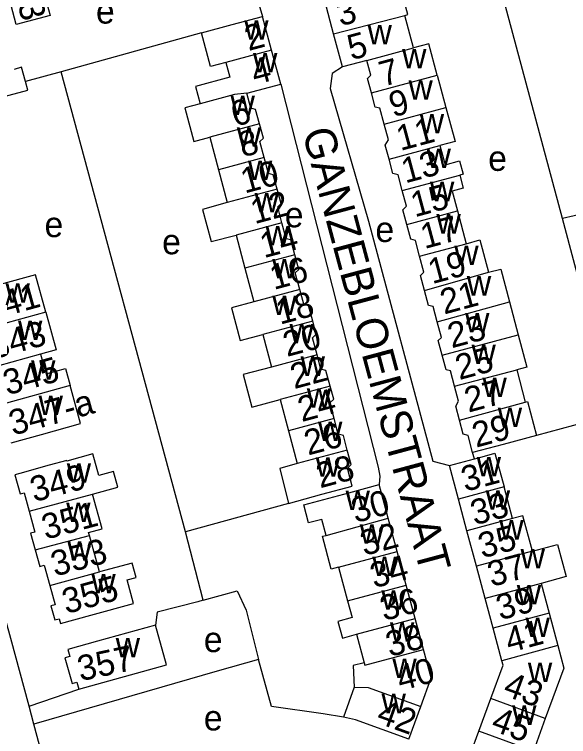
# Model space of a CAD drawing. Extents: x 161258 to 163262, y 380749 to 382054.
# Drawn here: x 162637.4 to 162725.4, y 380891.5 to 381006.1 of the extents above; entities that cross this region are included whole.
import ezdxf

# ---------------------------------------------------------------- set-up
doc = ezdxf.new("R2010")
doc.units = 0
for name, color, linetype in [('BLT_Basislijn', 7, 'Continuous'), ('BLT_Bebouwing', 7, 'Continuous'), ('BLT_Centroide', 7, 'Continuous'), ('BLT_Huisnummer', 7, 'Continuous'), ('BLT_Huisnummer_ tussenligend', 7, 'Continuous'), ('BLT_Huisnummer_reeks', 7, 'Continuous'), ('BLT_Onderverdeling_panden', 7, 'Continuous'), ('BLT_Straatnaam', 7, 'Continuous')]:
    doc.layers.add(name, color=color, linetype=linetype)

msp = doc.modelspace()

# ---------------------------------------------------------------- linework, layer by layer
at = {"layer": 'BLT_Basislijn'}
for p, q in [((162724.48, 380973.67), (162713.31, 381015.17)), ((162674.73, 381012.76), (162676.84, 381005.77)), ((162667.15, 381003.17), (162644.85, 380996.98)), ((162644.85, 380996.98), (162639.18, 380995.41)), ((162664.6, 380923.97), (162644.85, 380996.98)), ((162738.59, 380976.98), (162724.48, 380973.67)), ((162732.68, 380942.59), (162724.48, 380973.67)), ((162732.68, 380942.59), (162720.33, 380939.28)), ((162710.47, 380935.55), (162710.2, 380936.55)), ((162680.95, 380928.49), (162664.6, 380923.97)), ((162667.42, 380913.11), (162664.6, 380923.97)), ((162639.76, 380896.31), (162647.65, 380898.99)), ((162640.53, 380893.46), (162639.76, 380896.31)), ((162646.34, 380871.78), (162640.53, 380893.46))]:
    msp.add_line(p, q, dxfattribs=at)
for points in [[(162689.52, 380997.74), (162687.88, 380996.7), (162687.56, 380994.31), (162693.67, 380973.26), (162703.88, 380935.18), (162706.51, 380934.49)], [(162679.72, 380995.02), (162695.2, 380934.23), (162695.46, 380932.82), (162695.37, 380931.47)], [(162639.76, 380896.31), (162636.88, 380907.05), (162625.03, 380949.86)], [(162667.42, 380913.11), (162672.8, 380914.62), (162674.21, 380911.55), (162676.21, 380903.73)], [(162667.42, 380913.11), (162666.57, 380912.87), (162660.1, 380911.24), (162659.85, 380909.16)], [(162676.21, 380903.73), (162669.64, 380901.86), (162640.53, 380893.46)], [(162689.67, 380894.55), (162686.48, 380895.11), (162678.27, 380896.25), (162676.21, 380903.73)]]:
    msp.add_lwpolyline(points, dxfattribs=at)
at = {"layer": 'BLT_Bebouwing'}
for p, q in [((162688.11, 381002.99), (162686.7, 381008.23)), ((162678.28, 381000.39), (162676.84, 381005.77)), ((162700.82, 381000.78), (162699.43, 381005.93)), ((162689.52, 380997.74), (162688.11, 381002.99)), ((162693.4, 380998.78), (162689.52, 380997.74)), ((162704.57, 380996.45), (162705.95, 380991.32)), ((162674.32, 380993.57), (162679.72, 380995.02)), ((162668.45, 380986.62), (162669.84, 380981.43)), ((162669.84, 380981.43), (162671.24, 380976.22)), ((162707.79, 380974.9), (162709.19, 380969.69)), ((162672.63, 380971.04), (162674.03, 380965.83)), ((162674.03, 380965.83), (162675.47, 380960.45)), ((162716.04, 380960.49), (162717.45, 380955.25)), ((162676.86, 380955.28), (162678.24, 380950.12)), ((162717.19, 380949.69), (162718.54, 380944.53)), ((162679.63, 380944.95), (162680.95, 380940.01)), ((162680.95, 380940.01), (162682.34, 380934.82)), ((162706.51, 380934.49), (162710.47, 380935.55)), ((162707.95, 380929.16), (162706.51, 380934.49)), ((162696.79, 380926.16), (162695.37, 380931.47)), ((162716.52, 380926.09), (162715.18, 380931.1)), ((162709.3, 380924.14), (162707.95, 380929.16)), ((162698.22, 380920.85), (162696.79, 380926.16)), ((162710.82, 380918.5), (162709.3, 380924.14)), ((162650.95, 380917.62), (162649.35, 380923.41)), ((162699.64, 380915.53), (162698.22, 380920.85)), ((162712.19, 380913.4), (162710.82, 380918.5)), ((162721.06, 380915.79), (162722.33, 380911.06)), ((162701.07, 380910.22), (162699.64, 380915.53)), ((162713.46, 380908.68), (162712.19, 380913.4)), ((162722.33, 380911.06), (162723.72, 380905.91)), ((162702.38, 380905.32), (162701.07, 380910.22)), ((162661.6, 380902.84), (162659.85, 380909.16)), ((162691.75, 380907.72), (162692.97, 380903.16)), ((162714.85, 380903.52), (162713.46, 380908.68)), ((162691.38, 380899.3), (162689.67, 380894.55)), ((162711.2, 380892.35), (162713.09, 380897.51)), ((162700.09, 380891.07), (162701.95, 380896.24)), ((162721.74, 380894.33), (162719.84, 380889.17)), ((162709.3, 380887.18), (162711.2, 380892.35))]:
    msp.add_line(p, q, dxfattribs=at)
for points in [[(162642.56, 381007.8), (162643.1, 381005.89), (162637.72, 381004.46), (162636.43, 381009.32), (162635.76, 381011.85)], [(162699.43, 381005.93), (162699.91, 381006.06), (162698.47, 381011.4)], [(162667.15, 381003.17), (162672.01, 381004.47), (162676.84, 381005.77)], [(162671.01, 380998.44), (162668.59, 380997.8), (162667.15, 381003.17)], [(162704.57, 380996.45), (162703.22, 381001.43), (162700.82, 381000.78)], [(162679.72, 380995.02), (162678.38, 381000.01), (162678.28, 381000.39)], [(162671.01, 380998.44), (162671.63, 380996.11), (162666.18, 380994.65), (162666.91, 380991.91)], [(162694.12, 380993.64), (162693.52, 380995.9), (162694.03, 380996.42), (162693.4, 380998.78)], [(162639.18, 380995.41), (162638.58, 380997.69), (162637.41, 380997.36)], [(162617.33, 380994.34), (162621.26, 380995.43), (162621.92, 380993.05), (162631.85, 380995.79), (162632.79, 380992.24), (162639.55, 380994.03), (162639.18, 380995.41)], [(162676.35, 380988.74), (162675.74, 380991.01), (162674.95, 380991.22), (162674.32, 380993.57)], [(162696.15, 380988.68), (162695.47, 380991.18), (162694.73, 380991.38), (162694.12, 380993.64)], [(162666.91, 380991.91), (162664.48, 380991.26), (162665.92, 380985.89), (162668.45, 380986.62)], [(162705.95, 380991.32), (162707.42, 380985.9), (162705, 380985.26)], [(162677.1, 380983.38), (162676.42, 380985.93), (162676.96, 380986.46), (162676.35, 380988.74)], [(162696.94, 380983.09), (162696.33, 380985.34), (162696.82, 380986.18), (162696.15, 380988.68)], [(162705, 380985.26), (162705.82, 380982.23), (162708.12, 380982.85), (162708.7, 380980.7), (162708.16, 380980.56)], [(162679.15, 380978.34), (162678.54, 380980.64), (162677.79, 380980.84), (162677.1, 380983.38)], [(162699.02, 380978.13), (162698.35, 380980.62), (162697.54, 380980.84), (162696.94, 380983.09)], [(162708.16, 380980.56), (162708.71, 380978.52), (162706.94, 380978.05), (162707.79, 380974.9)], [(162679.92, 380973), (162679.24, 380975.52), (162679.77, 380976.05), (162679.15, 380978.34)], [(162699.76, 380972.74), (162699.13, 380975.08), (162699.69, 380975.64), (162699.02, 380978.13)], [(162671.24, 380976.22), (162667.32, 380975.12), (162668.68, 380970.05), (162672.63, 380971.04)], [(162681.95, 380967.95), (162681.33, 380970.28), (162680.6, 380970.47), (162679.92, 380973)], [(162701.78, 380967.69), (162701.11, 380970.21), (162700.39, 380970.4), (162699.76, 380972.74)], [(162709.19, 380969.69), (162711.33, 380970.32), (162712.72, 380965.15)], [(162682.75, 380962.4), (162682.04, 380965.08), (162682.58, 380965.62), (162681.95, 380967.95)], [(162702.56, 380962.28), (162701.93, 380964.64), (162702.46, 380965.18), (162701.78, 380967.69)], [(162712.72, 380965.15), (162714.65, 380965.66), (162716.04, 380960.49)], [(162642.4, 380958.81), (162640.76, 380964.75), (162635.13, 380963.2), (162630.31, 380961.87)], [(162684.81, 380957.42), (162684.14, 380959.91), (162683.37, 380960.12), (162682.75, 380962.4)], [(162704.57, 380957.27), (162703.91, 380959.72), (162703.2, 380959.91), (162702.56, 380962.28)], [(162675.47, 380960.45), (162671.9, 380959.49), (162673.29, 380954.32), (162676.86, 380955.28)], [(162642.4, 380958.81), (162644.04, 380952.87), (162641.58, 380952.18)], [(162685.49, 380952.06), (162684.77, 380954.74), (162685.37, 380955.34), (162684.81, 380957.42)], [(162705.35, 380952), (162704.73, 380954.31), (162705.23, 380954.81), (162704.57, 380957.27)], [(162717.45, 380955.25), (162718.83, 380950.12), (162717.19, 380949.69)], [(162641.58, 380952.18), (162642.45, 380949.03), (162645.53, 380949.88), (162646.28, 380947.17)], [(162687.58, 380947.08), (162686.91, 380949.56), (162686.11, 380949.78), (162685.49, 380952.06)], [(162707.32, 380947.09), (162706.67, 380949.5), (162705.98, 380949.69), (162705.35, 380952)], [(162678.24, 380950.12), (162673.75, 380948.96), (162675.14, 380943.75), (162679.63, 380944.95)], [(162636.89, 380938.08), (162641.71, 380939.42), (162647.95, 380941.14), (162646.28, 380947.17)], [(162688.2, 380941.95), (162687.54, 380944.43), (162688.13, 380945.02), (162687.58, 380947.08)], [(162708.12, 380941.68), (162707.52, 380943.9), (162707.97, 380944.68), (162707.32, 380947.09)], [(162718.54, 380944.53), (162718.89, 380944.63), (162720.33, 380939.28)], [(162690.29, 380936.95), (162689.67, 380939.26), (162688.86, 380939.48), (162688.2, 380941.95)], [(162710.2, 380936.55), (162709.47, 380939.25), (162708.72, 380939.45), (162708.12, 380941.68)], [(162720.33, 380939.28), (162715.03, 380937.85), (162710.2, 380936.55)], [(162649.83, 380929.95), (162653.85, 380931.06), (162653.17, 380933.53), (162650.85, 380932.89), (162649.9, 380936.34), (162645.77, 380935.2), (162645.74, 380935.3), (162642.97, 380934.54), (162638.3, 380933.25)], [(162680.95, 380928.49), (162686.25, 380929.92), (162691.08, 380931.21), (162690.32, 380934.05), (162690.91, 380934.64), (162690.29, 380936.95)], [(162710.47, 380935.55), (162711.34, 380935.79), (162713.74, 380936.43), (162715.18, 380931.1)], [(162682.34, 380934.82), (162679.56, 380934.01), (162680.95, 380928.49)], [(162638.3, 380933.25), (162637.5, 380933.03), (162638.34, 380930.01), (162638.96, 380930.18), (162639.78, 380927.23)], [(162686.92, 380923.41), (162686.24, 380925.93), (162684.15, 380925.37), (162683.37, 380928.25), (162690.54, 380930.17), (162695.37, 380931.47)], [(162649.35, 380923.41), (162649.22, 380923.88), (162651.35, 380924.47), (162649.83, 380929.95)], [(162639.78, 380927.23), (162640.68, 380923.94), (162640, 380923.75), (162640.74, 380921.1)], [(162719.69, 380920.88), (162718.17, 380926.53), (162716.52, 380926.09)], [(162688.9, 380918.35), (162687.74, 380918.04), (162686.34, 380923.26), (162686.92, 380923.41)], [(162719.69, 380920.88), (162723.69, 380921.96), (162725.06, 380916.86), (162721.06, 380915.79)], [(162640.74, 380921.1), (162641.46, 380918.48), (162642.16, 380918.67), (162643.06, 380915.43)], [(162643.06, 380915.43), (162643.89, 380912.41), (162643.23, 380912.22), (162643.84, 380909.99), (162644.52, 380910.18), (162644.74, 380909.4), (162649.56, 380910.73), (162656.35, 380912.6), (162655.35, 380916.33), (162656.75, 380916.7), (162656.13, 380919.02), (162650.95, 380917.62)], [(162688.9, 380918.35), (162690.33, 380913.04)], [(162690.33, 380913.04), (162691.04, 380910.36), (162688.8, 380909.76), (162689.51, 380907.12), (162691.75, 380907.72)], [(162659.85, 380909.16), (162650.64, 380906.62), (162645.9, 380905.31), (162646.21, 380904.2), (162645.45, 380903.99), (162646.58, 380899.89), (162647.34, 380900.1), (162647.65, 380898.99)], [(162701.95, 380896.24), (162703.6, 380900.8), (162702.38, 380905.32)], [(162723.72, 380905.91), (162724.68, 380902.34), (162721.74, 380894.33)], [(162692.97, 380903.16), (162691.22, 380902.74), (162691.38, 380899.3)], [(162713.09, 380897.51), (162715.04, 380902.8), (162714.85, 380903.52)], [(162647.65, 380898.99), (162661.6, 380902.84)], [(162700.09, 380891.07), (162691.62, 380894.12), (162689.67, 380894.55)]]:
    msp.add_lwpolyline(points, dxfattribs=at)
at = {"layer": 'BLT_Onderverdeling_panden'}
for p, q in [((162688.11, 381002.99), (162699.43, 381005.93)), ((162693.4, 380998.78), (162700.82, 381000.78)), ((162678.28, 381000.39), (162671.01, 380998.44)), ((162694.12, 380993.64), (162704.57, 380996.45)), ((162696.15, 380988.68), (162705.95, 380991.32)), ((162676.35, 380988.74), (162668.45, 380986.62)), ((162696.94, 380983.09), (162705, 380985.26)), ((162677.1, 380983.38), (162669.84, 380981.43)), ((162699.02, 380978.13), (162708.16, 380980.56)), ((162679.15, 380978.34), (162671.24, 380976.22)), ((162699.76, 380972.74), (162707.79, 380974.9)), ((162679.92, 380973), (162672.63, 380971.04)), ((162701.78, 380967.69), (162709.19, 380969.69)), ((162681.95, 380967.95), (162674.03, 380965.83)), ((162702.56, 380962.28), (162712.72, 380965.15)), ((162682.75, 380962.4), (162675.47, 380960.45)), ((162704.57, 380957.27), (162716.04, 380960.49)), ((162642.4, 380958.81), (162631.98, 380955.93)), ((162684.81, 380957.42), (162676.86, 380955.28)), ((162705.35, 380952), (162717.45, 380955.25)), ((162641.58, 380952.18), (162633.62, 380949.98)), ((162685.49, 380952.06), (162678.24, 380950.12)), ((162707.32, 380947.09), (162717.19, 380949.69)), ((162646.28, 380947.17), (162635.24, 380944.11)), ((162687.58, 380947.08), (162679.63, 380944.95)), ((162708.12, 380941.68), (162718.54, 380944.53)), ((162688.2, 380941.95), (162680.95, 380940.01)), ((162690.29, 380936.95), (162682.34, 380934.82)), ((162715.18, 380931.1), (162707.95, 380929.16)), ((162639.78, 380927.23), (162649.83, 380929.95)), ((162686.92, 380923.41), (162696.79, 380926.16)), ((162716.52, 380926.09), (162709.3, 380924.14)), ((162640.74, 380921.1), (162649.35, 380923.41)), ((162688.9, 380918.35), (162698.22, 380920.85)), ((162719.69, 380920.88), (162710.82, 380918.5)), ((162643.06, 380915.43), (162650.95, 380917.62)), ((162721.06, 380915.79), (162712.19, 380913.4)), ((162690.33, 380913.04), (162699.64, 380915.53)), ((162691.75, 380907.72), (162701.07, 380910.22)), ((162721.74, 380894.33), (162713.09, 380897.51)), ((162719.84, 380889.17), (162711.2, 380892.35))]:
    msp.add_line(p, q, dxfattribs=at)
for points in [[(162674.32, 380993.57), (162672.37, 380993.37), (162666.91, 380991.91)], [(162722.33, 380911.06), (162713.46, 380908.68)], [(162692.97, 380903.16), (162693.07, 380902.82), (162702.38, 380905.32)], [(162723.72, 380905.91), (162714.85, 380903.52)], [(162691.38, 380899.3), (162693.62, 380899.24), (162701.95, 380896.24)]]:
    msp.add_lwpolyline(points, dxfattribs=at)

# ---------------------------------------------------------------- texts
at = {"layer": 'BLT_Centroide'}
for s, p in [('e', (162650.38, 381004.62)), ('w', (162673.93, 381002.09)), ('w', (162693.51, 381001.34)), ('w', (162699, 380997.53)), ('w', (162675.32, 380996.88)), ('w', (162700.01, 380992.56)), ('w', (162671.75, 380990.09)), ('w', (162701.8, 380987.19)), ('w', (162672.75, 380985.09)), ('w', (162702.88, 380981.69)), ('e', (162712.67, 380981.25)), ('w', (162674.52, 380979.81)), ('w', (162703.42, 380976.44)), ('w', (162675.56, 380974.69)), ('e', (162680.36, 380972.29)), ('w', (162704.45, 380971.31)), ('e', (162642.21, 380970.74)), ('e', (162694.76, 380969.96)), ('w', (162677.31, 380969.41)), ('e', (162660.89, 380968.01)), ('w', (162707.28, 380966.31)), ('w', (162678.37, 380964.19)), ('w', (162709.28, 380961.47)), ('w', (162636.02, 380960.34)), ('w', (162678.38, 380958.38)), ('w', (162709, 380955.62)), ('w', (162638, 380954.41)), ('w', (162681.12, 380953.88)), ('w', (162710.02, 380950.62)), ('w', (162640.08, 380948.12)), ('w', (162682.88, 380948.72)), ('w', (162711.76, 380945.38)), ('w', (162683.86, 380943.66)), ('w', (162641.27, 380942.5)), ('w', (162714.19, 380940.59)), ('w', (162685.65, 380938.38)), ('w', (162685.28, 380932.72)), ('w', (162710.84, 380932.78)), ('w', (162645.74, 380931.78)), ('w', (162712.28, 380927.47)), ('w', (162690.02, 380927.44)), ('w', (162645.65, 380925.53)), ('w', (162692.27, 380922.09)), ('w', (162714.43, 380922.75)), ('w', (162645.84, 380919.38)), ('w', (162717.81, 380918.16)), ('w', (162694.27, 380916.94)), ('w', (162649.65, 380914.22)), ('w', (162695.7, 380911.62)), ('w', (162717.21, 380912.44)), ('w', (162718.59, 380907.28)), ('w', (162697.07, 380906.53)), ('e', (162667.51, 380904.88)), ('w', (162653.51, 380904.06)), ('w', (162697.45, 380900.78)), ('w', (162718.97, 380900.12)), ('w', (162695.73, 380895.19)), ('w', (162716.47, 380893.34)), ('e', (162667.51, 380892.45))]:
    msp.add_text(s, height=4, dxfattribs=at).set_placement(p)
at = {"layer": 'BLT_Huisnummer'}
for s, rotation, p in [('153', 284.8549, (162636.4, 381013.42)), ('3', 15.0705, (162689.2, 381004.17)), ('2', 15.0123, (162674.61, 381000.26)), ('7', 15.071, (162695.97, 380994.59)), ('6', 15.019, (162672.44, 380988.23)), ('11', 15.0662, (162698.72, 380984.4)), ('10', 15.0152, (162673.99, 380977.64)), ('15', 15.0576, (162701, 380973.87)), ('14', 15.0205, (162677.05, 380967.38)), ('19', 15.0618, (162703.76, 380963.26)), ('341', 15.468, (162633.23, 380957.38)), ('18', 15.0019, (162679.59, 380956.82)), ('23', 15.0542, (162706.86, 380953.08)), ('22', 15.0096, (162681.85, 380946.6)), ('27', 15.0652, (162709.52, 380942.87)), ('26', 15.0027, (162684.06, 380936.07)), ('31', 15.0523, (162709.01, 380930.3)), ('349', 15.068, (162640.55, 380928.66)), ('30', 15.0119, (162691.58, 380925.34)), ('35', 15.0511, (162711.71, 380919.73)), ('34', 15.0144, (162694.55, 380915)), ('355', 15.437, (162645.65, 380910.9)), ('39', 15.0571, (162714.56, 380909.92)), ('38', 15.0144, (162697.02, 380904.08)), ('357', 12.0967, (162647.91, 380900.25)), ('43', 339.8, (162714.84, 380898.11)), ('42', 340.1743, (162694.73, 380893.73))]:
    msp.add_text(s, height=4, rotation=rotation, dxfattribs=at).set_placement(p)
at = {"layer": 'BLT_Huisnummer_ tussenligend'}
for s, rotation, p in [('5', 15.0705, (162690.93, 380998.78)), ('4', 15.0123, (162675.64, 380994.87)), ('9', 15.071, (162697.54, 380989.73)), ('8', 15.019, (162673.66, 380983.37)), ('13', 15.0662, (162699.5, 380979.25)), ('12', 15.0152, (162675.57, 380972.78)), ('17', 15.0576, (162702.55, 380968.83)), ('16', 15.0205, (162678.62, 380962.34)), ('21', 15.0618, (162705.66, 380958.44)), ('343', 15.468, (162634.18, 380951.35)), ('20', 15.0019, (162680.7, 380951.71)), ('25', 15.0542, (162708.08, 380948.04)), ('345', 15.468, (162636.27, 380945.61)), ('24', 15.0096, (162683.05, 380941.38)), ('29', 15.0652, (162710.74, 380937.31)), ('28', 15.0027, (162685.97, 380930.86)), ('33', 15.0523, (162710.49, 380924.97)), ('351', 15.068, (162642.38, 380922.7)), ('32', 15.0119, (162692.98, 380920.13)), ('353', 15.068, (162643.85, 380916.85)), ('37', 15.0511, (162713.19, 380915.21)), ('36', 15.0144, (162696.12, 380909.79)), ('41', 15.0571, (162716, 380904.75)), ('40', 15.0144, (162698.75, 380898.69)), ('45', 339.8, (162712.93, 380892.55))]:
    msp.add_text(s, height=4, rotation=rotation, dxfattribs=at).set_placement(p)
at = {"layer": 'BLT_Huisnummer_reeks'}
msp.add_text('347-a', height=4, rotation=15.4454, dxfattribs=at).set_placement((162637.2, 380939.22))
at = {"layer": 'BLT_Straatnaam'}
msp.add_text('GANZEBLOEMSTRAAT', height=5, rotation=285.0172, dxfattribs=at).set_placement((162683.11, 380987.44))

doc.saveas('drawing.dxf')
